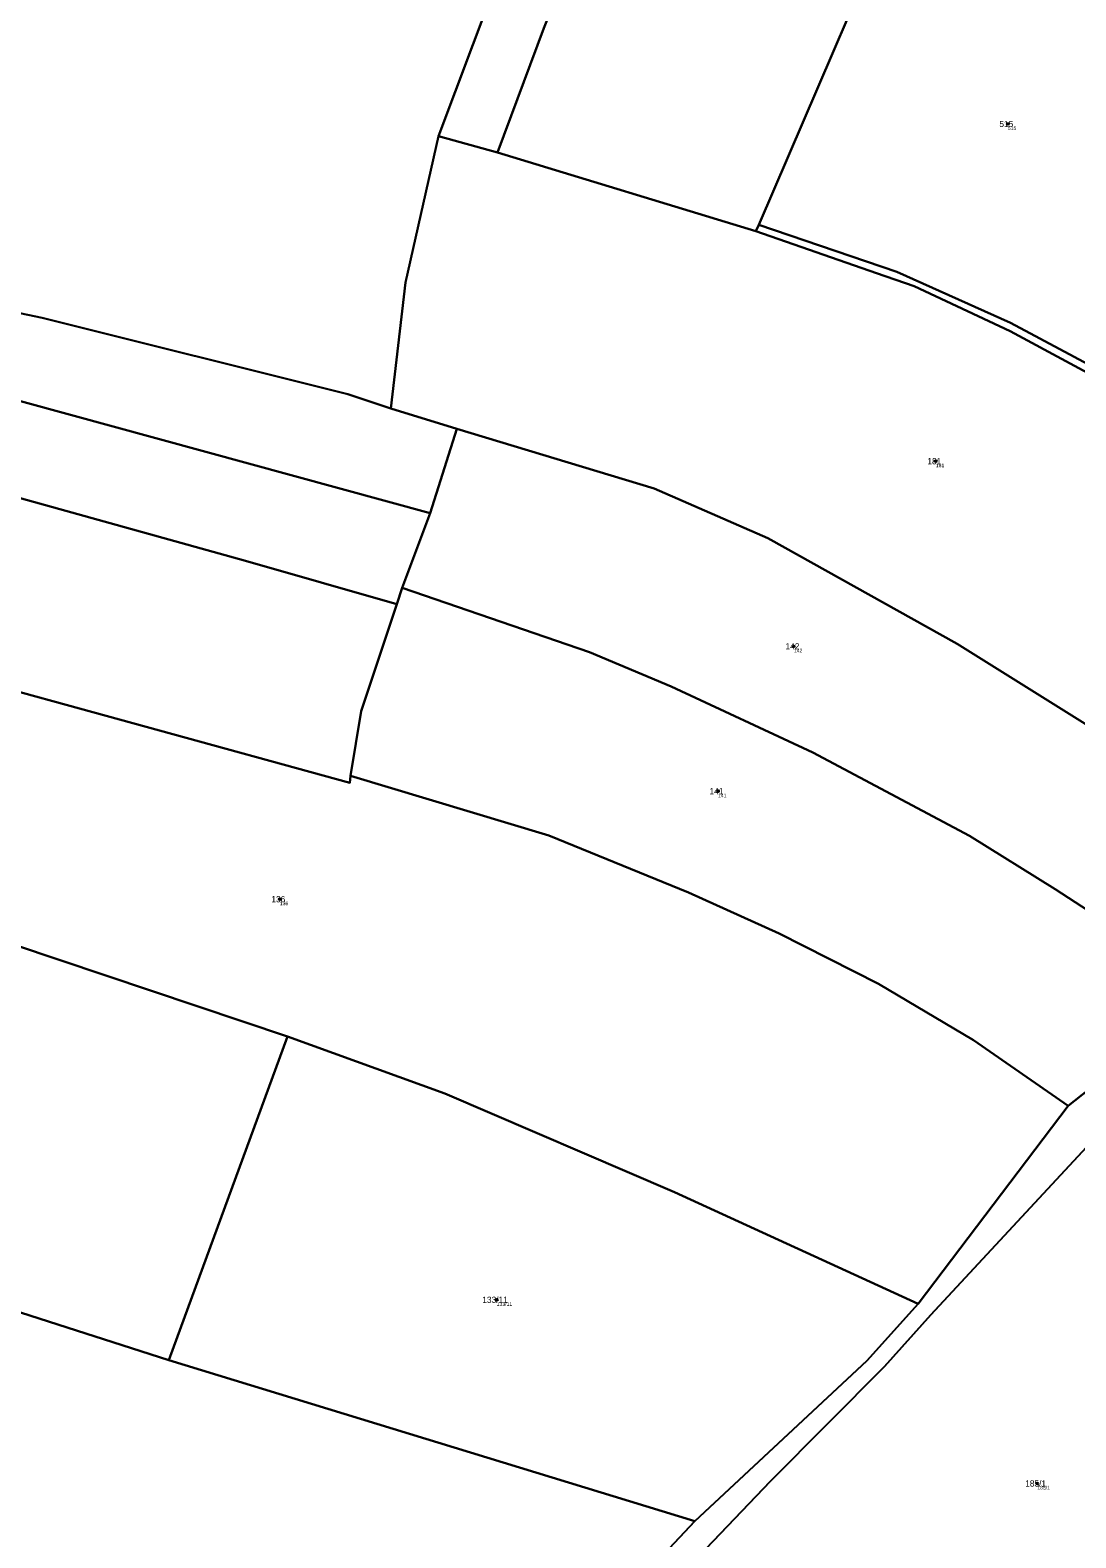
# Model space of a CAD drawing. Extents: x -700238 to -698499, y -1070626 to -1068006.
# Drawn here: x -699782.7 to -699496.9, y -1068910.8 to -1068498.7 of the extents above; entities that cross this region are included whole.
import ezdxf

# ---------------------------------------------------------------- set-up
doc = ezdxf.new("R2010")
doc.units = 0
for name, color, linetype in [('Definiční body', 7, 'Continuous'), ('Hranice parcel', 7, 'Continuous'), ('Parcelní čísla', 7, 'Continuous'), ('Polygon parcely', 7, 'Continuous')]:
    doc.layers.add(name, color=color, linetype=linetype)

msp = doc.modelspace()

# ---------------------------------------------------------------- linework, layer by layer
at = {"layer": 'Definiční body'}
for centre in [(-699515.44, -1068524.30994), (-699535.12, -1068616.48994), (-699573.92, -1068667.10994), (-699594.68, -1068706.71994), (-699714.46, -1068736.22994), (-699655.17, -1068845.74994), (-699507.4, -1068895.94994)]:
    msp.add_circle(centre, 0.25, dxfattribs=at)
at = {"layer": 'Hranice parcel'}
for p, q in [((-699671.14, -1068527.69), (-699657.18, -1068490.6)), ((-699671.14, -1068527.69), (-699655.01, -1068532.14)), ((-699655.01, -1068532.14), (-699584.32, -1068553.61)), ((-699583.54, -1068551.89), (-699584.32, -1068553.61)), ((-699666.08, -1068607.69), (-699684.13, -1068602.07)), ((-699666.08, -1068607.69), (-699673.34, -1068630.67)), ((-699673.34, -1068630.67), (-699681, -1068651.1)), ((-699681, -1068651.1), (-699682.47, -1068655.58)), ((-699744.81, -1068862.23), (-699712.36, -1068773.77)), ((-699498.94, -1068792.74), (-699539.98, -1068846.82)), ((-699871.66, -1068821.49), (-699744.81, -1068862.23)), ((-699601.04, -1068906.25), (-699744.81, -1068862.23))]:
    msp.add_line(p, q, dxfattribs=at)
for points in [[(-699655.01, -1068532.14), (-699642.31, -1068498.14), (-699613.14, -1068425.59), (-699572.66, -1068328.54)], [(-699583.54, -1068551.89), (-699538.81, -1068447.71), (-699534.75, -1068438.26)], [(-699684.13, -1068602.07), (-699680.08, -1068567.69), (-699671.14, -1068527.69)], [(-699489.31, -1068592.29), (-699514.72, -1068578.68), (-699545.8, -1068564.77), (-699583.54, -1068551.89)], [(-699911.29, -1068553.85), (-699895.28, -1068555.81), (-699839.16, -1068564.86), (-699779.49, -1068577.34), (-699695.89, -1068598.19), (-699684.13, -1068602.07)], [(-699584.32, -1068553.61), (-699551.31, -1068565.08), (-699541.03, -1068568.61), (-699514.77, -1068580.92), (-699467.93, -1068606.23), (-699418.44, -1068636.97), (-699391.79, -1068658.5), (-699420.37, -1068692.98), (-699440.37, -1068723.79)], [(-699673.34, -1068630.67), (-699809.75, -1068593.4), (-699854.26, -1068585.32), (-699920.53, -1068578.1), (-699975.6, -1068571.89)], [(-699682.47, -1068655.58), (-699723.86, -1068643.71), (-699810.1, -1068619.73), (-699858.93, -1068609.75), (-699910.04, -1068604.61)], [(-699440.37, -1068723.79), (-699482.65, -1068695.57), (-699529.3, -1068666.47), (-699581.06, -1068637.52), (-699612.14, -1068624.01), (-699666.08, -1068607.69)], [(-699695.12, -1068702.49), (-699695.35, -1068704.45), (-699806.82, -1068673.78), (-699874.22, -1068656.87), (-699901.88, -1068652.54)], [(-699464.55, -1068758.22), (-699502.54, -1068733.53), (-699525.94, -1068718.9), (-699568.74, -1068696.16), (-699607.46, -1068678.07), (-699629.84, -1068668.69), (-699681, -1068651.1)], [(-699695.12, -1068702.49), (-699692.25, -1068684.81), (-699682.47, -1068655.58)], [(-699498.94, -1068792.74), (-699524.87, -1068774.77), (-699550.82, -1068759.4), (-699577.98, -1068745.62), (-699602.77, -1068734.4), (-699640.97, -1068718.81), (-699695.12, -1068702.49)], [(-699712.36, -1068773.77), (-699886.67, -1068715.24), (-699906.69, -1068711.97)], [(-699464.55, -1068758.22), (-699476.32, -1068774.9), (-699498.94, -1068792.74)], [(-699539.98, -1068846.82), (-699606.54, -1068816.32), (-699669.4, -1068789.37), (-699712.36, -1068773.77)], [(-699467.03, -1068777.07), (-699469.58, -1068780.23), (-699489.21, -1068798.95), (-699536.5, -1068849.9), (-699549.19, -1068864.03), (-699580.35, -1068895.36), (-699603.8, -1068919.93)], [(-699539.98, -1068846.82), (-699554.03, -1068862.47), (-699601.04, -1068906.25)], [(-699601.04, -1068906.25), (-699627.54, -1068934.54), (-699674.11, -1068982.48), (-699685.64, -1068993.9), (-699702.78, -1069019.04), (-699717.64, -1069038.19)]]:
    msp.add_lwpolyline(points, dxfattribs=at)
at = {"layer": 'Polygon parcely'}
for points in [[(-699572.66, -1068328.54), (-699573.62, -1068327.95), (-699591.24, -1068317.17), (-699608.73, -1068359.75), (-699623.95, -1068401.12), (-699627.99, -1068411.98), (-699655.97, -1068487.17), (-699657.18, -1068490.6), (-699671.14, -1068527.69), (-699655.01, -1068532.14), (-699642.31, -1068498.14), (-699613.14, -1068425.59)], [(-699655.01, -1068532.14), (-699584.32, -1068553.61), (-699583.54, -1068551.89), (-699538.81, -1068447.71), (-699534.75, -1068438.26), (-699499.35, -1068355.82), (-699498.53, -1068353.82), (-699513.83, -1068348.95), (-699554.94, -1068335.25), (-699572.66, -1068328.54), (-699613.14, -1068425.59), (-699642.31, -1068498.14)], [(-699955.93, -1068372.18), (-700009.61, -1068354.69), (-700046.18, -1068345.86), (-700040.87, -1068359.92), (-700034.51, -1068382.29), (-700033.18, -1068393.26), (-700008.42, -1068397.14), (-699968.89, -1068409.59), (-699915.7, -1068430.51), (-699875.35, -1068449.22), (-699911.29, -1068553.85), (-699895.28, -1068555.81), (-699839.16, -1068564.86), (-699779.49, -1068577.34), (-699695.89, -1068598.19), (-699684.13, -1068602.07), (-699680.08, -1068567.69), (-699671.14, -1068527.69), (-699657.18, -1068490.6), (-699745.37, -1068463.45), (-699826.68, -1068428.95), (-699890.63, -1068400.44)], [(-699459.74, -1068489.07), (-699534.75, -1068438.26), (-699538.81, -1068447.71), (-699583.54, -1068551.89), (-699545.8, -1068564.77), (-699514.72, -1068578.68), (-699489.31, -1068592.29), (-699448.71, -1068496.54)], [(-699684.13, -1068602.07), (-699666.08, -1068607.69), (-699612.14, -1068624.01), (-699581.06, -1068637.52), (-699529.3, -1068666.47), (-699482.65, -1068695.57), (-699440.37, -1068723.79), (-699420.37, -1068692.98), (-699391.79, -1068658.5), (-699418.44, -1068636.97), (-699467.93, -1068606.23), (-699514.77, -1068580.92), (-699541.03, -1068568.61), (-699551.31, -1068565.08), (-699584.32, -1068553.61), (-699655.01, -1068532.14), (-699671.14, -1068527.69), (-699680.08, -1068567.69)], [(-699666.08, -1068607.69), (-699684.13, -1068602.07), (-699695.89, -1068598.19), (-699779.49, -1068577.34), (-699839.16, -1068564.86), (-699895.28, -1068555.81), (-699911.29, -1068553.85), (-699993.45, -1068545.35), (-699975.6, -1068571.89), (-699920.53, -1068578.1), (-699854.26, -1068585.32), (-699809.75, -1068593.4), (-699673.34, -1068630.67)], [(-699809.75, -1068593.4), (-699854.26, -1068585.32), (-699920.53, -1068578.1), (-699975.6, -1068571.89), (-699957.99, -1068598.81), (-699943.73, -1068599.96), (-699910.04, -1068604.61), (-699858.93, -1068609.75), (-699810.1, -1068619.73), (-699723.86, -1068643.71), (-699682.47, -1068655.58), (-699681, -1068651.1), (-699673.34, -1068630.67)], [(-699695.12, -1068702.49), (-699692.25, -1068684.81), (-699682.47, -1068655.58), (-699723.86, -1068643.71), (-699810.1, -1068619.73), (-699858.93, -1068609.75), (-699910.04, -1068604.61), (-699901.88, -1068652.54), (-699874.22, -1068656.87), (-699806.82, -1068673.78), (-699695.35, -1068704.45)], [(-699673.34, -1068630.67), (-699681, -1068651.1), (-699629.84, -1068668.69), (-699607.46, -1068678.07), (-699568.74, -1068696.16), (-699525.94, -1068718.9), (-699502.54, -1068733.53), (-699464.55, -1068758.22), (-699440.37, -1068723.79), (-699482.65, -1068695.57), (-699529.3, -1068666.47), (-699581.06, -1068637.52), (-699612.14, -1068624.01), (-699666.08, -1068607.69)], [(-699695.12, -1068702.49), (-699695.35, -1068704.45), (-699806.82, -1068673.78), (-699874.22, -1068656.87), (-699901.88, -1068652.54), (-699922.93, -1068651.13), (-699916.99, -1068669.78), (-699911.75, -1068696.8), (-699906.69, -1068711.97), (-699886.67, -1068715.24), (-699712.36, -1068773.77), (-699669.4, -1068789.37), (-699606.54, -1068816.32), (-699539.98, -1068846.82), (-699498.94, -1068792.74), (-699524.87, -1068774.77), (-699550.82, -1068759.4), (-699577.98, -1068745.62), (-699602.77, -1068734.4), (-699640.97, -1068718.81)], [(-699682.47, -1068655.58), (-699692.25, -1068684.81), (-699695.12, -1068702.49), (-699640.97, -1068718.81), (-699602.77, -1068734.4), (-699577.98, -1068745.62), (-699550.82, -1068759.4), (-699524.87, -1068774.77), (-699498.94, -1068792.74), (-699476.32, -1068774.9), (-699464.55, -1068758.22), (-699502.54, -1068733.53), (-699525.94, -1068718.9), (-699568.74, -1068696.16), (-699607.46, -1068678.07), (-699629.84, -1068668.69), (-699681, -1068651.1)], [(-699906.69, -1068711.97), (-699894.97, -1068748.83), (-699871.66, -1068821.49), (-699744.81, -1068862.23), (-699712.36, -1068773.77), (-699886.67, -1068715.24)], [(-699601.04, -1068906.25), (-699554.03, -1068862.47), (-699539.98, -1068846.82), (-699606.54, -1068816.32), (-699669.4, -1068789.37), (-699712.36, -1068773.77), (-699744.81, -1068862.23)], [(-699536.5, -1068849.9), (-699549.19, -1068864.03), (-699580.35, -1068895.36), (-699603.8, -1068919.93), (-699588.42, -1068936.57), (-699577.66, -1068955.53), (-699570.69, -1068974.98), (-699564.08, -1068981.34), (-699516.89, -1068958.22), (-699501.19, -1068954.74), (-699489.25, -1068955.25), (-699477.59, -1068953.57), (-699466.57, -1068947.54), (-699450.3, -1068923.87), (-699434.9, -1068894.43), (-699437.02, -1068860.08), (-699421.12, -1068856.29), (-699417.46, -1068845.03), (-699436.71, -1068810.63), (-699444.09, -1068780.91), (-699467.03, -1068777.07), (-699469.58, -1068780.23), (-699489.21, -1068798.95)], [(-699601.04, -1068906.25), (-699744.81, -1068862.23), (-699871.66, -1068821.49), (-699865.04, -1068834.97), (-699857.58, -1068850.39), (-699844.44, -1068871.08), (-699816.47, -1068910.26), (-699808.84, -1068926.02), (-699798.2, -1068962), (-699790.22, -1068999.77), (-699784.18, -1069015.11), (-699717.64, -1069038.19), (-699702.78, -1069019.04), (-699685.64, -1068993.9), (-699674.11, -1068982.48), (-699627.54, -1068934.54)]]:
    msp.add_lwpolyline(points, close=True, dxfattribs=at)
for points in [[(-699489.31, -1068592.29), (-699514.72, -1068578.68), (-699545.8, -1068564.77), (-699583.54, -1068551.89), (-699584.32, -1068553.61), (-699551.31, -1068565.08), (-699541.03, -1068568.61), (-699514.77, -1068580.92), (-699467.93, -1068606.23)], [(-699476.32, -1068774.9), (-699498.94, -1068792.74), (-699539.98, -1068846.82), (-699554.03, -1068862.47), (-699601.04, -1068906.25), (-699627.54, -1068934.54)], [(-699603.8, -1068919.93), (-699580.35, -1068895.36), (-699549.19, -1068864.03), (-699536.5, -1068849.9), (-699489.21, -1068798.95)]]:
    msp.add_lwpolyline(points, dxfattribs=at)

# ---------------------------------------------------------------- texts
at = {"layer": 'Definiční body'}
for s, p in [('515', (-699515.44, -1068525.966)), ('181', (-699535.12, -1068618.146)), ('142', (-699573.92, -1068668.766)), ('141', (-699594.68, -1068708.376)), ('136', (-699714.46, -1068737.886)), ('133/11', (-699655.17, -1068847.406)), ('185/1', (-699507.4, -1068897.606))]:
    msp.add_text(s, height=0.999996, dxfattribs=at).set_placement(p)
at = {"layer": 'Parcelní čísla'}
for s, p in [('515', (-699517.765, -1068525.16)), ('181', (-699537.445, -1068617.34)), ('142', (-699576.245, -1068667.96)), ('141', (-699597.005, -1068707.57)), ('136', (-699716.785, -1068737.08)), ('133/11', (-699659.117, -1068846.6)), ('185/1', (-699510.698, -1068896.8))]:
    msp.add_text(s, height=1.699998, dxfattribs=at).set_placement(p)

doc.saveas('drawing.dxf')
